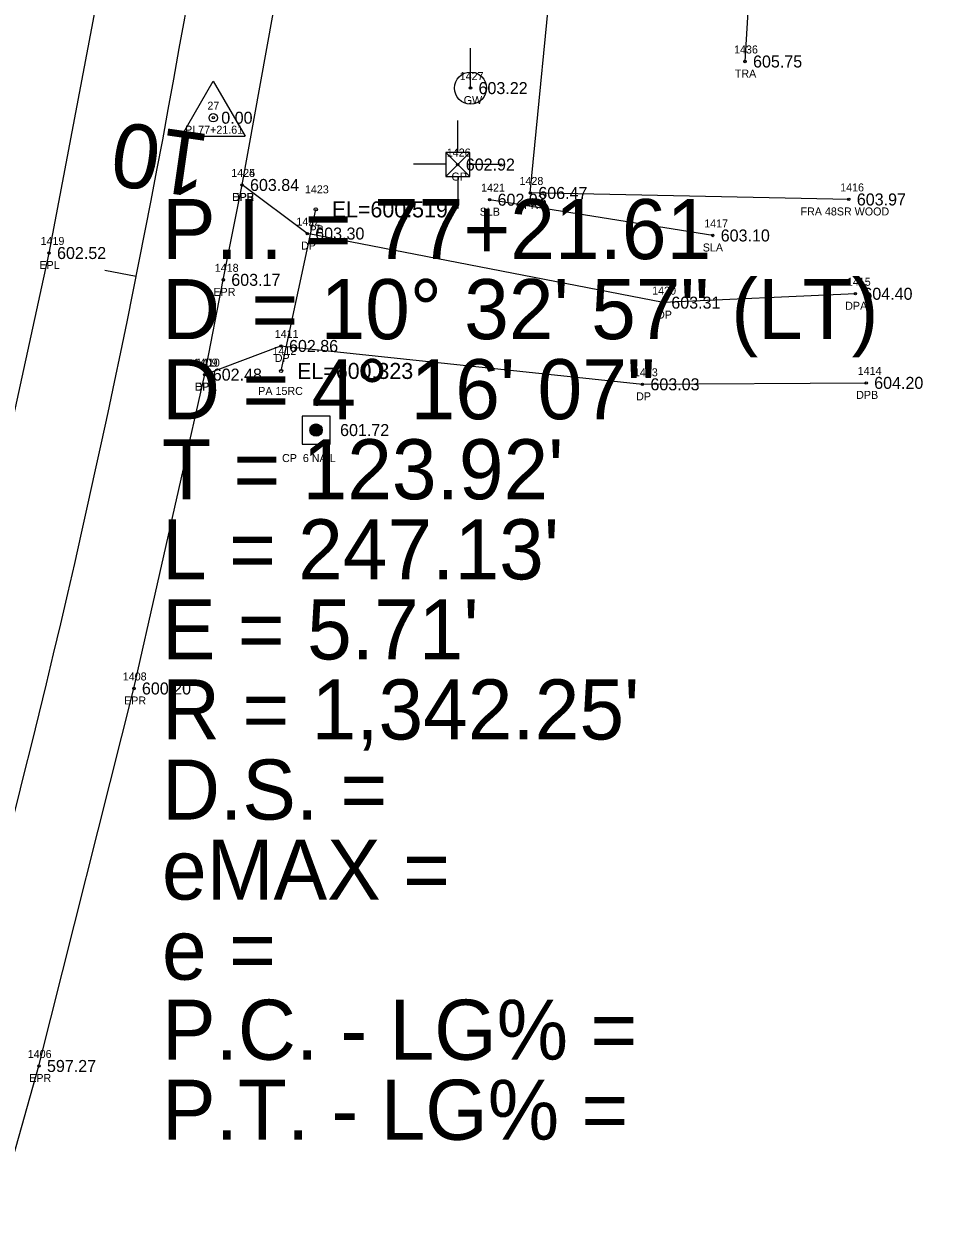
# Model space of a CAD drawing. Extents: x 1694813 to 1696862, y 1086485 to 1091027.
# Drawn here: x 1695795.7 to 1695910.8, y 1089706.2 to 1089855.4 of the extents above; entities that cross this region are included whole.
import ezdxf

# ---------------------------------------------------------------- set-up
doc = ezdxf.new("R2010")
doc.units = 0
for name, color, linetype in [('RD_EX_DR_Pipe', 7, 'Continuous'), ('RD_EX_DR_Pipe_txCode', 7, 'Continuous'), ('RD_EX_Driveway', 7, 'Continuous'), ('RD_EX_Driveway_txCode', 7, 'Continuous'), ('RD_EX_Fence_Other', 7, 'Continuous'), ('RD_EX_Fence_Other_txCode', 7, 'Continuous'), ('RD_EX_Road', 7, 'Continuous'), ('RD_EX_Road_txCode', 7, 'Continuous'), ('RD_EX_TX_Driveway_ELEV', 7, 'Continuous'), ('RD_EX_TX_Fence_Other_ELEV', 7, 'Continuous'), ('RD_EX_TX_Road_ELEV', 7, 'Continuous'), ('RD_EX_TX_UT_ELEV', 7, 'Continuous'), ('RD_EX_TX_VEG_ELEV', 7, 'Continuous'), ('RD_EX_UT', 7, 'Continuous'), ('RD_EX_UT_txCode', 7, 'Continuous'), ('RD_EX_VEG', 7, 'Continuous'), ('RD_EX_VEG_txCode', 7, 'Continuous'), ('RD_HC_Cl', 7, 'Continuous'), ('RD_HC_Data', 7, 'Continuous'), ('RD_HC_Data_Tic', 7, 'Continuous'), ('RD_HC_Survey', 7, 'Continuous'), ('RD_HC_Survey_ELEV', 7, 'Continuous'), ('RD_HC_Survey_txCode', 7, 'Continuous'), ('RD_HC_TX_Sta50', 7, 'Continuous'), ('RD_HC_txCode', 7, 'Continuous'), ('RD_SMD_Locator', 7, 'Continuous'), ('RD_TX_Pipe_ElevEX', 7, 'Continuous')]:
    doc.layers.add(name, color=color, linetype=linetype)

msp = doc.modelspace()

# ---------------------------------------------------------------- linework, layer by layer
at = {"layer": 'RD_EX_DR_Pipe'}
msp.add_line((1695827.87, 1089812.03), (1695832.2, 1089832.21), dxfattribs=at)
at = {"layer": 'RD_EX_Driveway'}
for points in [[(1695899.6, 1089821.67), (1695875.61, 1089820.56), (1695831.14, 1089829.19), (1695822.99, 1089835.26)], [(1695818.34, 1089811.57), (1695827.86, 1089815.15), (1695873, 1089810.36), (1695900.95, 1089810.54)]]:
    msp.add_lwpolyline(points, dxfattribs=at)
at = {"layer": 'RD_EX_Fence_Other'}
msp.add_lwpolyline([(1695898.78, 1089833.45), (1695859, 1089834.26), (1695862.01, 1089865.39), (1695867.57, 1089916.68), (1695873.04, 1089973.43), (1695877.77, 1090016.67), (1695879.63, 1090038.73)], dxfattribs=at)
at = {"layer": 'RD_EX_Road'}
for points in [[(1695813.78, 1089148.1), (1695805.56, 1089142.08), (1695776.44, 1089183.94), (1695749.27, 1089231.88), (1695730.49, 1089275.72), (1695714.87, 1089332.12), (1695707.87, 1089381.72), (1695706.58, 1089435.34), (1695711.58, 1089484.26), (1695722.15, 1089537.59), (1695749.04, 1089634.88), (1695776.11, 1089730.43), (1695788.13, 1089777.42), (1695798.89, 1089826.76), (1695807.1, 1089870.03), (1695814.71, 1089923.3), (1695820.51, 1089978.16), (1695824.04, 1090019.79), (1695832.76, 1090119.06), (1695841.25, 1090216.76), (1695850.36, 1090314.41), (1695859.24, 1090411.82), (1695868.09, 1090511.63), (1695876.75, 1090608.38)], [(1695735.35, 1089335.84), (1695728.69, 1089383.6), (1695727.9, 1089434.83), (1695732.68, 1089480.1), (1695743.4, 1089531.84), (1695770.35, 1089628.36), (1695797.63, 1089725.22), (1695809.49, 1089772.37), (1695818.34, 1089811.57), (1695820.65, 1089823.41), (1695822.99, 1089835.26), (1695829.18, 1089869.37), (1695836.32, 1089920.97), (1695842.44, 1089975.46), (1695846.49, 1090018.55), (1695849.32, 1090055.39), (1695850.91, 1090072.92), (1695855.09, 1090117.49), (1695863.53, 1090214.93), (1695872.56, 1090312.44), (1695881.69, 1090410.78), (1695890.45, 1090509.3), (1695899.01, 1090605.4)]]:
    msp.add_lwpolyline(points, dxfattribs=at)
at = {"layer": 'RD_EX_UT'}
for p, q in [((1695851.53, 1089847.36), (1695851.53, 1089852.36)), ((1695849.94, 1089839.31), (1695849.94, 1089843.31)), ((1695851.44, 1089839.31), (1695848.44, 1089836.31)), ((1695848.44, 1089839.31), (1695851.44, 1089836.31)), ((1695851.44, 1089839.31), (1695848.44, 1089839.31)), ((1695848.44, 1089839.31), (1695848.44, 1089836.31)), ((1695851.44, 1089836.31), (1695851.44, 1089839.31)), ((1695848.42, 1089837.86), (1695844.42, 1089837.86)), ((1695851.46, 1089837.87), (1695855.47, 1089837.87)), ((1695848.44, 1089836.31), (1695851.44, 1089836.31)), ((1695849.94, 1089836.31), (1695849.94, 1089832.31))]:
    msp.add_line(p, q, dxfattribs=at)
msp.add_circle((1695851.53, 1089847.36), 2, dxfattribs=at)
at = {"layer": 'RD_EX_VEG'}
msp.add_line((1695881.78, 1089828.95), (1695853.91, 1089833.42), dxfattribs=at)
msp.add_lwpolyline([(1695885.82, 1089850.68), (1695893.09, 1089970.88), (1695893.02, 1090013.82), (1695904.28, 1090114.68), (1695866.77, 1090153.16), (1695876.29, 1090212.72), (1695880.67, 1090311.3), (1695888, 1090410.55), (1695898.84, 1090510.09), (1695910.81, 1090607.5)], dxfattribs=at)
at = {"layer": 'RD_HC_Cl'}
msp.add_arc((1694493.64, 1090087.29), 1342.25, 344.31262, 354.86182, dxfattribs=at)
at = {"layer": 'RD_HC_Data'}
for p, q in [((1695815.43, 1089841.37), (1695819.4, 1089848.24)), ((1695819.4, 1089848.24), (1695823.37, 1089841.37)), ((1695815.43, 1089841.37), (1695823.37, 1089841.37))]:
    msp.add_line(p, q, dxfattribs=at)
msp.add_circle((1695819.4, 1089843.66), 0.529, dxfattribs=at)
at = {"layer": 'RD_HC_Data_Tic'}
msp.add_line((1695809.78, 1089823.81), (1695805.86, 1089824.59), dxfattribs=at)
at = {"layer": 'RD_HC_Survey'}
for p, q in [((1695831.79, 1089804.03), (1695831.79, 1089805.28)), ((1695831.81, 1089804.01), (1695831.81, 1089805.3)), ((1695831.84, 1089804), (1695831.84, 1089805.31)), ((1695831.86, 1089803.98), (1695831.86, 1089805.33)), ((1695831.89, 1089803.97), (1695831.89, 1089805.34)), ((1695831.91, 1089803.96), (1695831.91, 1089805.35)), ((1695831.93, 1089803.95), (1695831.93, 1089805.36)), ((1695831.96, 1089803.94), (1695831.96, 1089805.37)), ((1695831.98, 1089803.93), (1695831.98, 1089805.38)), ((1695832.01, 1089803.92), (1695832.01, 1089805.39)), ((1695832.03, 1089803.91), (1695832.03, 1089805.4)), ((1695832.06, 1089803.91), (1695832.06, 1089805.4)), ((1695832.08, 1089803.9), (1695832.08, 1089805.41)), ((1695832.11, 1089803.9), (1695832.11, 1089805.41)), ((1695832.13, 1089803.89), (1695832.13, 1089805.42)), ((1695832.16, 1089803.89), (1695832.16, 1089805.42)), ((1695832.18, 1089803.89), (1695832.18, 1089805.42)), ((1695832.21, 1089803.89), (1695832.21, 1089805.42)), ((1695832.23, 1089803.89), (1695832.23, 1089805.42)), ((1695832.26, 1089803.89), (1695832.26, 1089805.42)), ((1695832.28, 1089803.89), (1695832.28, 1089805.42)), ((1695832.31, 1089803.89), (1695832.31, 1089805.42)), ((1695832.33, 1089803.89), (1695832.33, 1089805.42)), ((1695832.36, 1089803.89), (1695832.36, 1089805.42)), ((1695832.38, 1089803.9), (1695832.38, 1089805.41)), ((1695832.41, 1089803.9), (1695832.41, 1089805.41)), ((1695832.43, 1089803.91), (1695832.43, 1089805.4)), ((1695832.45, 1089803.92), (1695832.45, 1089805.39)), ((1695832.48, 1089803.92), (1695832.48, 1089805.39)), ((1695832.5, 1089803.93), (1695832.5, 1089805.38)), ((1695832.53, 1089803.94), (1695832.53, 1089805.37)), ((1695832.55, 1089803.95), (1695832.55, 1089805.36)), ((1695832.58, 1089803.96), (1695832.58, 1089805.34)), ((1695832.6, 1089803.98), (1695832.6, 1089805.33)), ((1695832.63, 1089803.99), (1695832.63, 1089805.32)), ((1695832.65, 1089804.01), (1695832.65, 1089805.3)), ((1695832.68, 1089804.02), (1695832.68, 1089805.29)), ((1695832.7, 1089804.04), (1695832.7, 1089805.27)), ((1695831.49, 1089804.48), (1695831.49, 1089804.83)), ((1695831.51, 1089804.39), (1695831.51, 1089804.92)), ((1695831.54, 1089804.33), (1695831.54, 1089804.98)), ((1695831.56, 1089804.28), (1695831.56, 1089805.03)), ((1695831.59, 1089804.24), (1695831.59, 1089805.07)), ((1695831.61, 1089804.21), (1695831.61, 1089805.1)), ((1695831.64, 1089804.17), (1695831.64, 1089805.14)), ((1695831.66, 1089804.14), (1695831.66, 1089805.17)), ((1695831.69, 1089804.12), (1695831.69, 1089805.19)), ((1695831.71, 1089804.09), (1695831.71, 1089805.22)), ((1695831.74, 1089804.07), (1695831.74, 1089805.24)), ((1695831.76, 1089804.05), (1695831.76, 1089805.26)), ((1695832.73, 1089804.06), (1695832.73, 1089805.25)), ((1695832.75, 1089804.08), (1695832.75, 1089805.23)), ((1695832.78, 1089804.11), (1695832.78, 1089805.2)), ((1695832.8, 1089804.13), (1695832.8, 1089805.18)), ((1695832.83, 1089804.16), (1695832.83, 1089805.15)), ((1695832.85, 1089804.19), (1695832.85, 1089805.12)), ((1695832.88, 1089804.22), (1695832.88, 1089805.09)), ((1695832.9, 1089804.26), (1695832.9, 1089805.05)), ((1695832.92, 1089804.31), (1695832.92, 1089805)), ((1695832.95, 1089804.36), (1695832.95, 1089804.95)), ((1695832.97, 1089804.43), (1695832.97, 1089804.88)), ((1695833, 1089804.54), (1695833, 1089804.77))]:
    msp.add_line(p, q, dxfattribs=at)
msp.add_lwpolyline([(1695833.99, 1089806.4), (1695830.49, 1089806.4), (1695830.49, 1089802.9), (1695833.99, 1089802.9)], close=True, dxfattribs=at)
msp.add_circle((1695832.24, 1089804.65), 0.769, dxfattribs=at)
at = {"layer": 'RD_SMD_Locator'}
for centre, radius in [((1695885.82, 1089850.68), 0.15), ((1695851.53, 1089847.36), 0.15), ((1695819.4, 1089843.66), 0.15), ((1695849.94, 1089837.81), 0.15), ((1695822.99, 1089835.26), 0.15), ((1695822.99, 1089835.26), 0.15), ((1695859, 1089834.26), 0.15), ((1695832.2, 1089832.21), 0.2), ((1695853.91, 1089833.42), 0.15), ((1695898.78, 1089833.45), 0.15), ((1695831.14, 1089829.19), 0.15), ((1695881.78, 1089828.95), 0.15), ((1695798.89, 1089826.76), 0.15), ((1695820.65, 1089823.41), 0.15), ((1695899.6, 1089821.67), 0.15), ((1695875.61, 1089820.56), 0.15), ((1695827.86, 1089815.15), 0.15), ((1695818.34, 1089811.57), 0.15), ((1695818.34, 1089811.57), 0.15), ((1695827.87, 1089812.03), 0.2), ((1695873, 1089810.36), 0.15), ((1695900.95, 1089810.54), 0.15), ((1695832.24, 1089804.65), 0.15), ((1695809.49, 1089772.37), 0.15), ((1695797.63, 1089725.22), 0.15)]:
    msp.add_circle(centre, radius, dxfattribs=at)

# ---------------------------------------------------------------- texts
at = {"layer": 'RD_EX_DR_Pipe_txCode'}
for s, p in [('1423', (1695830.85, 1089834.21)), ('PB', (1695831.42, 1089829.21)), ('1412', (1695826.8, 1089814.03)), ('PA 15RC', (1695825.02, 1089809.03))]:
    msp.add_text(s, height=1, dxfattribs=at).set_placement(p)
at = {"layer": 'RD_EX_Driveway_txCode'}
for s, p in [('1424', (1695821.65, 1089836.26)), ('DPB', (1695821.74, 1089833.26)), ('1422', (1695829.79, 1089830.19)), ('DP', (1695830.36, 1089827.19)), ('1415', (1695898.54, 1089822.67)), ('1420', (1695874.22, 1089821.56)), ('DPA', (1695898.33, 1089819.67)), ('DP', (1695874.83, 1089818.56)), ('1411', (1695827.08, 1089816.15)), ('1410', (1695817.24, 1089812.57)), ('DP', (1695827.08, 1089813.15)), ('1413', (1695871.94, 1089811.36)), ('1414', (1695899.89, 1089811.54)), ('DPA', (1695817.08, 1089809.57)), ('DP', (1695872.22, 1089808.36)), ('DPB', (1695899.7, 1089808.54))]:
    msp.add_text(s, height=1, dxfattribs=at).set_placement(p)
at = {"layer": 'RD_EX_Fence_Other_txCode'}
for s, p in [('1428', (1695857.65, 1089835.26)), ('1416', (1695897.7, 1089834.45)), ('FR', (1695858.24, 1089832.26)), ('FRA 48SR WOOD', (1695892.75, 1089831.45))]:
    msp.add_text(s, height=1, dxfattribs=at).set_placement(p)
at = {"layer": 'RD_EX_Road_txCode'}
for s, p in [('1425', (1695821.65, 1089836.26)), ('EPR', (1695821.77, 1089833.26)), ('1419', (1695797.83, 1089827.76)), ('EPL', (1695797.69, 1089824.76)), ('1418', (1695819.59, 1089824.41)), ('EPR', (1695819.42, 1089821.41)), ('1409', (1695816.96, 1089812.57)), ('EPR', (1695817.11, 1089809.57)), ('1408', (1695808.1, 1089773.37)), ('EPR', (1695808.26, 1089770.37)), ('1406', (1695796.23, 1089726.22)), ('EPR', (1695796.41, 1089723.22))]:
    msp.add_text(s, height=1, dxfattribs=at).set_placement(p)
at = {"layer": 'RD_EX_TX_Driveway_ELEV'}
for s, p in [('603.84', (1695823.99, 1089834.51)), ('603.30', (1695832.14, 1089828.44)), ('604.40', (1695900.6, 1089820.92)), ('603.31', (1695876.61, 1089819.81)), ('602.86', (1695828.86, 1089814.4)), ('602.48', (1695819.34, 1089810.82)), ('604.20', (1695901.95, 1089809.79)), ('603.03', (1695874, 1089809.61))]:
    msp.add_text(s, height=1.5, dxfattribs=at).set_placement(p)
at = {"layer": 'RD_EX_TX_Fence_Other_ELEV'}
for s, p in [('606.47', (1695860, 1089833.51)), ('603.97', (1695899.78, 1089832.7))]:
    msp.add_text(s, height=1.5, dxfattribs=at).set_placement(p)
at = {"layer": 'RD_EX_TX_Road_ELEV'}
for s, p in [('603.84', (1695823.99, 1089834.51)), ('602.52', (1695799.89, 1089826.01)), ('603.17', (1695821.65, 1089822.66)), ('602.48', (1695819.34, 1089810.82)), ('600.20', (1695810.49, 1089771.62)), ('597.27', (1695798.63, 1089724.47))]:
    msp.add_text(s, height=1.5, dxfattribs=at).set_placement(p)
at = {"layer": 'RD_EX_TX_UT_ELEV'}
for s, p in [('603.22', (1695852.53, 1089846.61)), ('602.92', (1695850.94, 1089837.06))]:
    msp.add_text(s, height=1.5, dxfattribs=at).set_placement(p)
at = {"layer": 'RD_EX_TX_VEG_ELEV'}
for s, p in [('605.75', (1695886.82, 1089849.93)), ('602.93', (1695854.91, 1089832.67)), ('603.10', (1695882.78, 1089828.2))]:
    msp.add_text(s, height=1.5, dxfattribs=at).set_placement(p)
at = {"layer": 'RD_EX_UT_txCode'}
for s, p in [('1427', (1695850.18, 1089848.36)), ('GW', (1695850.68, 1089845.36)), ('1426', (1695848.57, 1089838.81)), ('GP', (1695849.16, 1089835.81))]:
    msp.add_text(s, height=1, dxfattribs=at).set_placement(p)
at = {"layer": 'RD_EX_VEG_txCode'}
for s, p in [('1436', (1695884.45, 1089851.68)), ('TRA', (1695884.54, 1089848.68)), ('1421', (1695852.85, 1089834.42)), ('SLB', (1695852.68, 1089831.42)), ('1417', (1695880.72, 1089829.95)), ('SLA', (1695880.54, 1089826.95))]:
    msp.add_text(s, height=1, dxfattribs=at).set_placement(p)
at = {"layer": 'RD_HC_Data'}
for s, p in [('P.I. = 77+21.61', (1695813, 1089826)), ('D', (1695813, 1089816)), ('    = 10%%d 32\' 57" (LT)', (1695813, 1089816)), ('D = 4%%d 16\' 07"', (1695813, 1089806)), ("T = 123.92'", (1695813, 1089796)), ("L = 247.13'", (1695813, 1089786)), ("E = 5.71'", (1695813, 1089776)), ("R = 1,342.25'", (1695813, 1089766)), ('D.S. = ', (1695813, 1089756)), ('eMAX = ', (1695813, 1089746)), ('e = ', (1695813, 1089736)), ('P.C. - LG% = ', (1695813, 1089726)), ('P.T. - LG% = ', (1695813, 1089716))]:
    msp.add_text(s, height=7.5, dxfattribs=at).set_placement(p)
at = {"layer": 'RD_HC_Survey_ELEV'}
for s, p in [('0.00', (1695820.4, 1089842.91)), ('601.72', (1695835.24, 1089803.9))]:
    msp.add_text(s, height=1.5, dxfattribs=at).set_placement(p)
at = {"layer": 'RD_HC_Survey_txCode'}
for s, p in [('6', (1695831.93, 1089807.65)), ('CP  6 NAIL', (1695827.99, 1089800.65))]:
    msp.add_text(s, height=1, dxfattribs=at).set_placement(p)
at = {"layer": 'RD_HC_TX_Sta50'}
msp.add_text('10', height=8, rotation=171.8225, dxfattribs=at).set_placement((1695819.15, 1089841.53))
at = {"layer": 'RD_HC_txCode'}
for s, p in [('27', (1695818.67, 1089844.66)), ('PI 77+21.61', (1695815.88, 1089841.66))]:
    msp.add_text(s, height=1, dxfattribs=at).set_placement(p)
at = {"layer": 'RD_TX_Pipe_ElevEX'}
for s, p in [('EL=600.519', (1695834.2, 1089831.21)), ('EL=600.323', (1695829.87, 1089811.03))]:
    msp.add_text(s, height=2, dxfattribs=at).set_placement(p)

doc.saveas('drawing.dxf')
